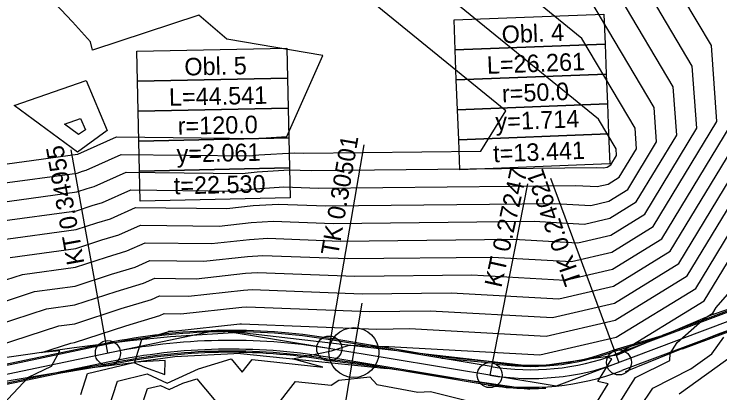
# Model space of a CAD drawing. Extents: x -549394 to -546608, y -1037055 to -1033629.
# Drawn here: x -547954.3 to -547813.1, y -1035552.4 to -1035476.6 of the extents above; entities that cross this region are included whole.
import ezdxf

# ---------------------------------------------------------------- set-up
doc = ezdxf.new("R2010")
doc.units = 0
for name, color, linetype in [('hlavni_vrst', 7, 'Continuous'), ('hrana_L', 7, 'Continuous'), ('norm_vrst', 7, 'Continuous'), ('POLYGONY_SITUACE_PO', 7, 'Continuous'), ('u_sirka_1_5m', 7, 'Continuous'), ('x_navrh_C11', 7, 'Continuous'), ('x_osa_C11', 7, 'Continuous'), ('x_popis_oblouky_C11', 7, 'Continuous'), ('x_popis_pricne_rezy_C11', 7, 'Continuous')]:
    doc.layers.add(name, color=color, linetype=linetype)

msp = doc.modelspace()

# ---------------------------------------------------------------- linework, layer by layer
at = {"layer": 'hlavni_vrst'}
for p, q in [((-547840.71, -1035481.45), (-547867.13, -1035459.91)), ((-547830.08, -1035499.36), (-547840.71, -1035481.45)), ((-547824.74, -1035521.56), (-547809.72, -1035496.69)), ((-547829.79, -1035503.49), (-547830.08, -1035499.36)), ((-547833.24, -1035509.2), (-547829.79, -1035503.49)), ((-547835.5, -1035510.59), (-547833.24, -1035509.2)), ((-547936.63, -1035514.26), (-547930.95, -1035511.74)), ((-547930.95, -1035511.74), (-547910.19, -1035511.96)), ((-547910.19, -1035511.96), (-547906.08, -1035511.51)), ((-547906.08, -1035511.51), (-547900.33, -1035511.14)), ((-547900.33, -1035511.14), (-547893.43, -1035511.4)), ((-547893.43, -1035511.4), (-547841.96, -1035510.86)), ((-547841.96, -1035510.86), (-547837.67, -1035511.09)), ((-547837.67, -1035511.09), (-547835.5, -1035510.59)), ((-547938.68, -1035514.88), (-547936.63, -1035514.26)), ((-547959.92, -1035518.38), (-547941.82, -1035515.91)), ((-547941.82, -1035515.91), (-547938.68, -1035514.88)), ((-547834.58, -1035527.6), (-547824.74, -1035521.56)), ((-547816.24, -1035533.92), (-547808.19, -1035520.58)), ((-547917.89, -1035529.51), (-547908, -1035528.43)), ((-547908, -1035528.43), (-547905.62, -1035528.27)), ((-547905.62, -1035528.27), (-547886.12, -1035529.02)), ((-547886.12, -1035529.02), (-547862.75, -1035528.77)), ((-547862.75, -1035528.77), (-547844.06, -1035529.8)), ((-547844.06, -1035529.8), (-547834.58, -1035527.6)), ((-547928.44, -1035530.43), (-547926.17, -1035529.42)), ((-547926.17, -1035529.42), (-547917.89, -1035529.51)), ((-547933.85, -1035532.06), (-547928.44, -1035530.43)), ((-547942.12, -1035534.75), (-547933.85, -1035532.06)), ((-547833.67, -1035544.62), (-547816.24, -1035533.92)), ((-547971.98, -1035543.39), (-547947.79, -1035535.53)), ((-547947.79, -1035535.53), (-547942.12, -1035534.75)), ((-547837.57, -1035550.06), (-547834.74, -1035545.54)), ((-547835.99, -1035545.15), (-547833.67, -1035544.62)), ((-547834.74, -1035545.54), (-547835.99, -1035545.15)), ((-547920.56, -1035550.43), (-547917.73, -1035549.55)), ((-547917.73, -1035549.55), (-547907.28, -1035562)), ((-547890.88, -1035550.84), (-547889.33, -1035549.83)), ((-547889.33, -1035549.83), (-547883.16, -1035549.18)), ((-547883.16, -1035549.18), (-547881.77, -1035550.67)), ((-547927.62, -1035551.49), (-547925.04, -1035550.88)), ((-547925.04, -1035550.88), (-547923.29, -1035551.66)), ((-547923.29, -1035551.66), (-547920.56, -1035550.43)), ((-547907.28, -1035562), (-547898.01, -1035550.06)), ((-547898.01, -1035550.06), (-547890.88, -1035550.84)), ((-547881.77, -1035550.67), (-547873.55, -1035552.25)), ((-547841.25, -1035559.8), (-547835.48, -1035550.56)), ((-547835.48, -1035550.56), (-547837.57, -1035550.06)), ((-547934.4, -1035572.05), (-547927.62, -1035551.49)), ((-547873.55, -1035552.25), (-547871.03, -1035552.06)), ((-547871.03, -1035552.06), (-547864.06, -1035553.84))]:
    msp.add_line(p, q, dxfattribs=at)
at = {"layer": 'hrana_L'}
for p, q in [((-547814.39, -1035536.61), (-547792.64, -1035529.21)), ((-547813.58, -1035540.62), (-547792.07, -1035532.74)), ((-547814.39, -1035536.61), (-547833.66, -1035544.82)), ((-547923, -1035541.16), (-547931.07, -1035541.92)), ((-547909.34, -1035540.3), (-547923, -1035541.16)), ((-547880.04, -1035543.67), (-547909.34, -1035540.3)), ((-547832.01, -1035548.06), (-547813.58, -1035540.62)), ((-547931.07, -1035541.92), (-547942.25, -1035543.35)), ((-547942.25, -1035543.35), (-547972.47, -1035547.64)), ((-547849.99, -1035547.16), (-547880.04, -1035543.67)), ((-547922.15, -1035545.14), (-547930.35, -1035546.27)), ((-547909.02, -1035544.46), (-547922.15, -1035545.14)), ((-547909.02, -1035544.46), (-547879.65, -1035547.5)), ((-547833.66, -1035544.82), (-547849.99, -1035547.16)), ((-547942.64, -1035547.74), (-547930.35, -1035546.27)), ((-547971.54, -1035552.66), (-547942.64, -1035547.74)), ((-547851.13, -1035551.7), (-547879.65, -1035547.5))]:
    msp.add_line(p, q, dxfattribs=at)
at = {"layer": 'norm_vrst'}
for p, q in [((-547818.64, -1035486.96), (-547842.87, -1035446.11)), ((-547822.45, -1035491.09), (-547847.35, -1035449.13)), ((-547814.82, -1035482.83), (-547832.98, -1035452.22)), ((-547826.27, -1035495.23), (-547844.03, -1035465.29)), ((-547837.4, -1035497.6), (-547874.77, -1035467.13)), ((-547942.62, -1035478.12), (-547948.01, -1035472.3)), ((-547855.94, -1035495.94), (-547882.42, -1035474.36)), ((-547917.35, -1035476.78), (-547938.59, -1035483.78)), ((-547911.72, -1035481.6), (-547917.35, -1035476.78)), ((-547939, -1035482.08), (-547942.62, -1035478.12)), ((-547938.59, -1035483.78), (-547939, -1035482.08)), ((-547892.53, -1035484.87), (-547911.72, -1035481.6)), ((-547813.74, -1035498.05), (-547814.82, -1035482.83)), ((-547899.77, -1035501.03), (-547892.53, -1035484.87)), ((-547817.75, -1035499.41), (-547818.64, -1035486.96)), ((-547954.25, -1035494.86), (-547939.88, -1035489.82)), ((-547939.88, -1035489.82), (-547935.68, -1035499.84)), ((-547821.76, -1035500.77), (-547822.45, -1035491.09)), ((-547819.64, -1035528.97), (-547797.68, -1035492.6)), ((-547941.63, -1035504.16), (-547954.25, -1035494.86)), ((-547821.34, -1035526.5), (-547801.69, -1035493.96)), ((-547860.93, -1035503.98), (-547855.94, -1035495.94)), ((-547825.78, -1035502.13), (-547826.27, -1035495.23)), ((-547823.04, -1035524.03), (-547805.71, -1035495.32)), ((-547944.22, -1035498.58), (-547940.99, -1035497.45)), ((-547940.99, -1035497.45), (-547940.04, -1035499.7)), ((-547833.9, -1035503.49), (-547837.4, -1035497.6)), ((-547941.38, -1035500.67), (-547944.22, -1035498.58)), ((-547826.44, -1035519.09), (-547813.74, -1035498.05)), ((-547935.68, -1035499.84), (-547941.63, -1035504.16)), ((-547940.04, -1035499.7), (-547941.38, -1035500.67)), ((-547828.14, -1035516.62), (-547817.75, -1035499.41)), ((-547941.54, -1035504.56), (-547933.82, -1035501.13)), ((-547933.82, -1035501.13), (-547905.57, -1035501.43)), ((-547905.57, -1035501.43), (-547904.93, -1035501.36)), ((-547904.93, -1035501.36), (-547899.77, -1035501.03)), ((-547829.84, -1035514.15), (-547821.76, -1035500.77)), ((-547831.54, -1035511.67), (-547825.78, -1035502.13)), ((-547967.21, -1035508.09), (-547941.64, -1035504.6)), ((-547941.64, -1035504.6), (-547941.58, -1035504.58)), ((-547941.58, -1035504.58), (-547941.54, -1035504.56)), ((-547939.9, -1035507.8), (-547932.86, -1035504.66)), ((-547932.86, -1035504.66), (-547907.11, -1035504.94)), ((-547907.11, -1035504.94), (-547905.31, -1035504.74)), ((-547905.31, -1035504.74), (-547898.21, -1035504.29)), ((-547898.21, -1035504.29), (-547896.35, -1035504.36)), ((-547896.35, -1035504.36), (-547860.93, -1035503.98)), ((-547834.94, -1035506.73), (-547833.8, -1035504.85)), ((-547833.8, -1035504.85), (-547833.9, -1035503.49)), ((-547817.94, -1035531.44), (-547802.5, -1035505.87)), ((-547894.89, -1035507.88), (-547837.81, -1035507.28)), ((-547837.81, -1035507.28), (-547836.4, -1035507.35)), ((-547836.4, -1035507.35), (-547835.68, -1035507.19)), ((-547835.68, -1035507.19), (-547834.94, -1035506.73)), ((-547964.78, -1035511.52), (-547941.7, -1035508.37)), ((-547941.7, -1035508.37), (-547940.61, -1035508.01)), ((-547940.61, -1035508.01), (-547939.9, -1035507.8)), ((-547938.27, -1035511.03), (-547931.9, -1035508.2)), ((-547931.9, -1035508.2), (-547908.65, -1035508.45)), ((-547908.65, -1035508.45), (-547905.7, -1035508.13)), ((-547905.7, -1035508.13), (-547899.27, -1035507.71)), ((-547899.27, -1035507.71), (-547894.89, -1035507.88)), ((-547941.76, -1035512.14), (-547939.65, -1035511.45)), ((-547939.65, -1035511.45), (-547938.27, -1035511.03)), ((-547835.32, -1035513.99), (-547831.54, -1035511.67)), ((-547962.35, -1035514.95), (-547941.76, -1035512.14)), ((-547813.88, -1035535.29), (-547794.7, -1035513.03)), ((-547906.46, -1035514.89), (-547901.39, -1035514.57)), ((-547901.39, -1035514.57), (-547891.96, -1035514.92)), ((-547891.96, -1035514.92), (-547846.12, -1035514.44)), ((-547846.12, -1035514.44), (-547838.95, -1035514.84)), ((-547838.95, -1035514.84), (-547835.32, -1035513.99)), ((-547835.13, -1035517.4), (-547829.84, -1035514.15)), ((-547934.99, -1035517.5), (-547929.99, -1035515.27)), ((-547929.99, -1035515.27), (-547911.73, -1035515.47)), ((-547911.73, -1035515.47), (-547906.46, -1035514.89)), ((-547937.71, -1035518.32), (-547934.99, -1035517.5)), ((-547840.23, -1035518.58), (-547835.13, -1035517.4)), ((-547834.95, -1035520.8), (-547828.14, -1035516.62)), ((-547941.88, -1035519.68), (-547937.71, -1035518.32)), ((-547933.35, -1035520.73), (-547929.04, -1035518.81)), ((-547929.04, -1035518.81), (-547913.27, -1035518.98)), ((-547913.27, -1035518.98), (-547906.85, -1035518.28)), ((-547906.85, -1035518.28), (-547902.45, -1035517.99)), ((-547902.45, -1035517.99), (-547890.5, -1035518.45)), ((-547890.5, -1035518.45), (-547850.28, -1035518.02)), ((-547850.28, -1035518.02), (-547840.23, -1035518.58)), ((-547957.5, -1035521.81), (-547941.88, -1035519.68)), ((-547834.77, -1035524.2), (-547826.44, -1035519.09)), ((-547941.94, -1035523.45), (-547936.75, -1035521.75)), ((-547936.75, -1035521.75), (-547933.35, -1035520.73)), ((-547914.81, -1035522.49), (-547907.23, -1035521.66)), ((-547907.23, -1035521.66), (-547903.51, -1035521.42)), ((-547903.51, -1035521.42), (-547889.04, -1035521.97)), ((-547889.04, -1035521.97), (-547854.43, -1035521.6)), ((-547854.43, -1035521.6), (-547841.51, -1035522.32)), ((-547841.51, -1035522.32), (-547834.95, -1035520.8)), ((-547931.71, -1035523.96), (-547928.08, -1035522.35)), ((-547928.08, -1035522.35), (-547914.81, -1035522.49)), ((-547955.07, -1035525.24), (-547941.94, -1035523.45)), ((-547935.78, -1035525.19), (-547931.71, -1035523.96)), ((-547842.78, -1035526.06), (-547834.77, -1035524.2)), ((-547834.4, -1035531.01), (-547823.04, -1035524.03)), ((-547942, -1035527.22), (-547935.78, -1035525.19)), ((-547930.08, -1035527.19), (-547927.13, -1035525.88)), ((-547927.13, -1035525.88), (-547916.35, -1035526)), ((-547916.35, -1035526), (-547907.61, -1035525.04)), ((-547907.61, -1035525.04), (-547904.57, -1035524.85)), ((-547904.57, -1035524.85), (-547887.58, -1035525.49)), ((-547887.58, -1035525.49), (-547858.59, -1035525.19)), ((-547858.59, -1035525.19), (-547842.78, -1035526.06)), ((-547952.64, -1035528.67), (-547942, -1035527.22)), ((-547934.81, -1035528.62), (-547930.08, -1035527.19)), ((-547834.22, -1035534.41), (-547821.34, -1035526.5)), ((-547970.96, -1035534.62), (-547952.64, -1035528.67)), ((-547942.06, -1035530.98), (-547934.81, -1035528.62)), ((-547834.04, -1035537.81), (-547819.64, -1035528.97)), ((-547950.21, -1035532.1), (-547942.06, -1035530.98)), ((-547908.38, -1035531.81), (-547906.68, -1035531.7)), ((-547906.68, -1035531.7), (-547884.66, -1035532.54)), ((-547845.34, -1035533.54), (-547834.4, -1035531.01)), ((-547833.85, -1035541.21), (-547817.94, -1035531.44)), ((-547971.47, -1035539), (-547950.21, -1035532.1)), ((-547926.8, -1035533.66), (-547925.22, -1035532.96)), ((-547925.22, -1035532.96), (-547919.43, -1035533.02)), ((-547919.43, -1035533.02), (-547908.38, -1035531.81)), ((-547884.66, -1035532.54), (-547866.9, -1035532.35)), ((-547866.9, -1035532.35), (-547845.34, -1035533.54)), ((-547932.88, -1035535.5), (-547926.8, -1035533.66)), ((-547846.62, -1035537.28), (-547834.22, -1035534.41)), ((-547942.17, -1035538.52), (-547932.88, -1035535.5)), ((-547920.97, -1035536.53), (-547908.76, -1035535.19)), ((-547908.76, -1035535.19), (-547907.74, -1035535.13)), ((-547907.74, -1035535.13), (-547883.2, -1035536.06)), ((-547883.2, -1035536.06), (-547871.06, -1035535.93)), ((-547871.06, -1035535.93), (-547846.62, -1035537.28)), ((-547814.54, -1035536.39), (-547813.88, -1035535.29)), ((-547931.91, -1035538.93), (-547925.16, -1035536.89)), ((-547925.16, -1035536.89), (-547924.26, -1035536.49)), ((-547924.26, -1035536.49), (-547920.97, -1035536.53)), ((-547821.64, -1035542.31), (-547816.07, -1035537.33)), ((-547816.07, -1035537.33), (-547814.54, -1035536.39)), ((-547945.36, -1035538.96), (-547942.17, -1035538.52)), ((-547922.51, -1035540.04), (-547909.14, -1035538.57)), ((-547909.14, -1035538.57), (-547908.8, -1035538.55)), ((-547908.8, -1035538.55), (-547881.74, -1035539.58)), ((-547847.89, -1035541.02), (-547834.04, -1035537.81)), ((-547971.78, -1035547.54), (-547945.36, -1035538.96)), ((-547942.23, -1035542.29), (-547931.91, -1035538.93)), ((-547928.74, -1035541.7), (-547923.52, -1035540.13)), ((-547923.52, -1035540.13), (-547923.31, -1035540.03)), ((-547923.31, -1035540.03), (-547922.51, -1035540.04)), ((-547881.74, -1035539.58), (-547875.22, -1035539.51)), ((-547875.22, -1035539.51), (-547847.89, -1035541.02)), ((-547849.17, -1035544.77), (-547833.85, -1035541.21)), ((-547814.73, -1035544.55), (-547812.35, -1035541.22)), ((-547948.71, -1035544.27), (-547942.93, -1035542.39)), ((-547942.93, -1035542.39), (-547942.23, -1035542.29)), ((-547930.13, -1035546.12), (-547928.74, -1035541.7)), ((-547890.82, -1035543.96), (-547887.25, -1035542.84)), ((-547887.25, -1035542.84), (-547880.27, -1035543.11)), ((-547823.1, -1035544.46), (-547821.64, -1035542.31)), ((-547945.14, -1035543.92), (-547948.71, -1035544.27)), ((-547946.79, -1035547.02), (-547945.14, -1035543.92)), ((-547898.59, -1035545.54), (-547890.82, -1035543.96)), ((-547880.27, -1035543.11), (-547879.37, -1035543.1)), ((-547879.37, -1035543.1), (-547849.17, -1035544.77)), ((-547917.38, -1035547.56), (-547910.87, -1035545.54)), ((-547910.87, -1035545.54), (-547908.65, -1035548.19)), ((-547908.65, -1035548.19), (-547906.68, -1035545.65)), ((-547906.68, -1035545.65), (-547892.57, -1035547.19)), ((-547892.57, -1035547.19), (-547898.59, -1035545.54)), ((-547823.16, -1035545.88), (-547823.1, -1035544.46)), ((-547821.28, -1035552.58), (-547810.32, -1035544.67)), ((-547818.92, -1035547.58), (-547814.73, -1035544.55)), ((-547951.44, -1035549.24), (-547946.79, -1035547.02)), ((-547939.59, -1035548.5), (-547930.32, -1035546.29)), ((-547930.32, -1035546.29), (-547928.24, -1035547.23)), ((-547930.12, -1035546.24), (-547930.13, -1035546.12)), ((-547924.1, -1035545.88), (-547930.12, -1035546.24)), ((-547928.24, -1035547.23), (-547924.12, -1035548.71)), ((-547924.12, -1035548.71), (-547924.1, -1035545.88)), ((-547829.99, -1035549.3), (-547823.16, -1035545.88)), ((-547940.97, -1035552.68), (-547939.59, -1035548.5)), ((-547933.6, -1035550), (-547927.68, -1035548.58)), ((-547927.68, -1035548.58), (-547923.65, -1035550.39)), ((-547923.65, -1035550.39), (-547917.38, -1035547.56)), ((-547826.56, -1035551.4), (-547818.92, -1035547.58)), ((-547966.24, -1035564.77), (-547951.44, -1035549.24)), ((-547937.68, -1035562.37), (-547933.6, -1035550)), ((-547830.95, -1035550.75), (-547829.99, -1035549.3)), ((-547837.42, -1035561.11), (-547830.95, -1035550.75)), ((-547829.15, -1035555.3), (-547826.56, -1035551.4))]:
    msp.add_line(p, q, dxfattribs=at)
at = {"layer": 'POLYGONY_SITUACE_PO'}
for centre in [(-547891.26, -1035543.48), (-547935.54, -1035544.41), (-547833.32, -1035546.27), (-547859.16, -1035548.81)]:
    msp.add_circle(centre, 2.5, dxfattribs=at)
at = {"layer": 'u_sirka_1_5m'}
msp.add_circle((-547886.32, -1035544.3), 5, dxfattribs=at)
at = {"layer": 'x_navrh_C11'}
for p, q in [((-547763.41, -1035518.04), (-547833.94, -1035544.64)), ((-547762.18, -1035521.32), (-547832.71, -1035547.91)), ((-547772.86, -1035521.34), (-547824.66, -1035540.87)), ((-547762.09, -1035521.55), (-547820.66, -1035543.64)), ((-547868.7, -1035545.2), (-547890.94, -1035541.51)), ((-547834.26, -1035543.77), (-547824.66, -1035540.87)), ((-547834.18, -1035544.01), (-547824.58, -1035541.11)), ((-547935.9, -1035542.7), (-548046.92, -1035565.96)), ((-547858.87, -1035547.09), (-547890.98, -1035541.75)), ((-547891.61, -1035545.58), (-547881.69, -1035546.85)), ((-547859.45, -1035550.54), (-547891.55, -1035545.21)), ((-547858.76, -1035546.43), (-547868.74, -1035545.45)), ((-547858.73, -1035546.18), (-547868.7, -1035545.2)), ((-547935.18, -1035546.12), (-548046.21, -1035569.4)), ((-547935.1, -1035546.49), (-547944.97, -1035548.17)), ((-547935.06, -1035546.74), (-547944.92, -1035548.42)), ((-547891.65, -1035545.83), (-547881.72, -1035547.09)), ((-547859.49, -1035550.79), (-547881.72, -1035547.09))]:
    msp.add_line(p, q, dxfattribs=at)
for points in [[(-547935.95, -1035542.45), (-548046.97, -1035565.71)], [(-547944.92, -1035548.42), (-548036.2, -1035567.54)]]:
    msp.add_lwpolyline(points, dxfattribs=at)
for centre, radius, start, end in [((-547910.93, -1035661.86), 122, 80.5677, 101.8343), ((-547910.93, -1035661.86), 121.75, 80.5677, 101.8343), ((-547910.93, -1035661.86), 118.25, 80.5677, 101.8343), ((-547910.93, -1035661.86), 117.87, 80.5677, 101.8343), ((-547910.93, -1035661.86), 117.62, 80.5654, 101.8366), ((-547850.96, -1035499.49), 47.58, 260.5677, 290.6607), ((-547850.96, -1035499.49), 47.33, 260.5576, 290.6708), ((-547850.96, -1035499.49), 48.25, 260.5677, 290.6607), ((-547850.96, -1035499.49), 51.75, 260.5677, 290.6607), ((-547850.96, -1035499.49), 52, 260.5677, 273.3393)]:
    msp.add_arc(centre, radius, start, end, dxfattribs=at)
at = {"layer": 'x_osa_C11'}
for points in [[(-547746.96, -1035513.71), (-547845.9, -1035551.02)], [(-547913.49, -1035539.79), (-548051.94, -1035568.8), (-548118.03, -1035610.76)], [(-547845.9, -1035551.02), (-547913.49, -1035539.79)]]:
    msp.add_lwpolyline(points, dxfattribs=at)
for centre, radius, start, end in [((-547910.93, -1035661.86), 120, 80.5677, 101.8343), ((-547850.96, -1035499.49), 50, 260.5677, 290.6607)]:
    msp.add_arc(centre, radius, start, end, dxfattribs=at)
at = {"layer": 'x_popis_oblouky_C11'}
for points in [[(-547866.3, -1035477.72), (-547836.32, -1035476.56), (-547836.09, -1035482.55), (-547866.07, -1035483.71)], [(-547929.72, -1035484), (-547899.73, -1035483.35), (-547899.6, -1035489.35), (-547929.59, -1035490)], [(-547866.07, -1035483.71), (-547836.09, -1035482.55), (-547835.86, -1035488.55), (-547865.84, -1035489.71)], [(-547929.59, -1035490), (-547899.6, -1035489.35), (-547899.47, -1035495.35), (-547929.46, -1035496)], [(-547865.84, -1035489.71), (-547835.86, -1035488.55), (-547835.63, -1035494.54), (-547865.6, -1035495.7)], [(-547865.6, -1035495.7), (-547835.63, -1035494.54), (-547835.39, -1035500.54), (-547865.37, -1035501.7)], [(-547929.46, -1035496), (-547899.47, -1035495.35), (-547899.34, -1035501.35), (-547929.33, -1035501.99)], [(-547865.37, -1035501.7), (-547835.39, -1035500.54), (-547835.16, -1035506.53), (-547865.14, -1035507.7)], [(-547929.33, -1035501.99), (-547899.34, -1035501.35), (-547899.21, -1035507.35), (-547929.2, -1035507.99)], [(-547929.2, -1035507.99), (-547899.21, -1035507.35), (-547899.08, -1035513.34), (-547929.07, -1035513.99)]]:
    msp.add_lwpolyline(points, close=True, dxfattribs=at)
for points in [[(-547891.26, -1035543.48), (-547884.25, -1035502.71)], [(-547935.54, -1035544.41), (-547942.89, -1035503.69)], [(-547846.98, -1035509.41), (-547833.32, -1035546.27)], [(-547851.6, -1035510.54), (-547859.16, -1035548.81)]]:
    msp.add_lwpolyline(points, dxfattribs=at)
at = {"layer": 'x_popis_pricne_rezy_C11'}
msp.add_lwpolyline([(-547887.96, -1035554.17), (-547886.32, -1035544.3), (-547884.68, -1035534.44)], dxfattribs=at)

# ---------------------------------------------------------------- texts
at = {"layer": 'x_popis_oblouky_C11'}
for s, rotation, p in [('Obl. 4', 2.24, (-547856.7, -1035482.4)), ('Obl. 5', 1.2583, (-547920.2, -1035488.85)), ('L=26.261', 2.24, (-547859.67, -1035488.52)), ('r=50.0', 2.24, (-547856.65, -1035494.24)), ('L=44.541', 1.2583, (-547923.28, -1035494.92)), ('y=1.714', 2.24, (-547857.95, -1035499.85)), ('r=120.0', 1.2583, (-547921.52, -1035500.71)), ('TK 0.30501', 80.2358, (-547889.5, -1035525.02)), ('t=13.441', 2.24, (-547858.4, -1035506.23)), ('KT 0.34955', 100.2372, (-547940.21, -1035526.42)), ('y=2.061', 1.2583, (-547921.75, -1035506.27)), ('KT 0.27247', 77.454, (-547856.84, -1035531.44)), ('TK 0.24621', 108.9562, (-547840.72, -1035530.18)), ('t=22.530', 1.2583, (-547922.31, -1035512.64))]:
    msp.add_text(s, height=3.5, rotation=rotation, dxfattribs=at).set_placement(p)

doc.saveas('drawing.dxf')
